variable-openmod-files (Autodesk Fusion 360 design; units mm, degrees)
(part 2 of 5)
sketch "Shell Hexagon Pattern" plane through (0, 0, 98) normal (0, 0, 1) x axis (-1, 0, 0)
  line L1 (19.1469, -26.6365) -> (22.8469, -28.7727)
  line L2 (19.1469, -22.3642) -> (19.1469, -26.6365)
  line L3 (22.8469, -20.228) -> (19.1469, -22.3642)
  line L4 (26.5469, -22.3642) -> (22.8469, -20.228)
  line L5 (26.5469, -26.6365) -> (26.5469, -22.3642)
  line L6 (22.8469, -28.7727) -> (26.5469, -26.6365)
  line L7 (-26.5469, 22.3642) -> (-22.8469, 20.228)
  line L8 (-26.5469, 26.6365) -> (-26.5469, 22.3642)
  line L9 (-22.8469, 28.7727) -> (-26.5469, 26.6365)
  line L10 (-19.1469, 26.6365) -> (-22.8469, 28.7727)
  line L11 (-19.1469, 22.3642) -> (-19.1469, 26.6365)
  line L12 (-22.8469, 20.228) -> (-19.1469, 22.3642)
  line L13 (19.1469, 22.3642) -> (22.8469, 20.228)
  line L14 (19.1469, 26.6365) -> (19.1469, 22.3642)
  line L15 (22.8469, 28.7727) -> (19.1469, 26.6365)
  line L16 (26.5469, 26.6365) -> (22.8469, 28.7727)
  line L17 (26.5469, 22.3642) -> (26.5469, 26.6365)
  line L18 (22.8469, 20.228) -> (26.5469, 22.3642)
  line L19 (-26.5469, -26.6365) -> (-22.8469, -28.7727)
  line L20 (-26.5469, -22.3642) -> (-26.5469, -26.6365)
  line L21 (-22.8469, -20.228) -> (-26.5469, -22.3642)
  line L22 (-19.1469, -22.3642) -> (-22.8469, -20.228)
  line L23 (-19.1469, -26.6365) -> (-19.1469, -22.3642)
  line L24 (-22.8469, -28.7727) -> (-19.1469, -26.6365)
  curve K1 (-7.3164, 50.178) -> (-7.3164, 50.178)
  line L25 (0, 51) -> (0, 0)
  line L26 (1, 24.5003) -> (0, 24.5003)
  line L27 (4.6, 24.5003) -> (1, 24.5003)
  line L28 (4.6, 20.3434) -> (1, 22.4219)
  line L29 (8.2, 22.4219) -> (4.6, 20.3434)
  line L30 (8.2, 26.5788) -> (8.2, 22.4219)
  line L31 (4.6, 28.6573) -> (8.2, 26.5788)
  line L32 (1, 26.5788) -> (4.6, 28.6573)
  line L33 (1, 22.4219) -> (1, 26.5788)
  line L34 (10.2, 24.5003) -> (8.2, 24.5003)
  line L35 (10.2, 26.5788) -> (13.8, 28.6573)
  line L36 (10.2, 22.4219) -> (10.2, 26.5788)
  line L37 (13.8, 20.3434) -> (10.2, 22.4219)
  line L38 (17.4, 22.4219) -> (13.8, 20.3434)
  line L39 (17.4, 26.5788) -> (17.4, 22.4219)
  line L40 (13.8, 28.6573) -> (17.4, 26.5788)
  line L41 (-1, 26.5788) -> (-1, 22.4219)
  line L42 (-4.6, 28.6573) -> (-1, 26.5788)
  line L43 (-8.2, 26.5788) -> (-4.6, 28.6573)
  line L44 (-8.2, 22.4219) -> (-8.2, 26.5788)
  line L45 (-4.6, 20.3434) -> (-8.2, 22.4219)
  line L46 (-1, 22.4219) -> (-4.6, 20.3434)
  line L47 (-13.8, 28.6573) -> (-10.2, 26.5788)
  line L48 (-17.4, 26.5788) -> (-13.8, 28.6573)
  line L49 (-17.4, 22.4219) -> (-17.4, 26.5788)
  line L50 (-13.8, 20.3434) -> (-17.4, 22.4219)
  line L51 (-10.2, 26.5788) -> (-10.2, 22.4219)
  line L52 (-10.2, 22.4219) -> (-13.8, 20.3434)
  line L53 (-1, 24.5003) -> (0, 24.5003)
  line L54 (16.6, 29.3501) -> (15.6, 27.618)
  line L55 (18.4, 28.3109) -> (14.8, 30.3893)
  line L56 (22, 30.3893) -> (18.4, 28.3109)
  line L57 (22, 34.5462) -> (22, 30.3893)
  line L58 (18.4, 36.6247) -> (22, 34.5462)
  line L59 (14.8, 34.5462) -> (18.4, 36.6247)
  line L60 (14.8, 30.3893) -> (14.8, 34.5462)
  line L61 (5.6, 30.3893) -> (5.6, 34.5462)
  line L62 (9.2, 28.3109) -> (5.6, 30.3893)
  line L63 (12.8, 30.3893) -> (9.2, 28.3109)
  line L64 (12.8, 34.5462) -> (12.8, 30.3893)
  line L65 (5.6, 34.5462) -> (9.2, 36.6247)
  line L66 (9.2, 36.6247) -> (12.8, 34.5462)
  line L67 (-3.6, 30.3893) -> (-3.6, 34.5462)
  line L68 (0, 28.3109) -> (-3.6, 30.3893)
  line L69 (3.6, 30.3893) -> (0, 28.3109)
  line L70 (3.6, 34.5462) -> (3.6, 30.3893)
  line L71 (-3.6, 34.5462) -> (0, 36.6247)
  line L72 (0, 36.6247) -> (3.6, 34.5462)
  line L73 (-12.8, 30.3893) -> (-12.8, 34.5462)
  line L74 (-9.2, 28.3109) -> (-12.8, 30.3893)
  line L75 (-5.6, 30.3893) -> (-9.2, 28.3109)
  line L76 (-5.6, 34.5462) -> (-5.6, 30.3893)
  line L77 (-12.8, 34.5462) -> (-9.2, 36.6247)
  line L78 (-9.2, 36.6247) -> (-5.6, 34.5462)
  line L79 (-14.8, 32.4678) -> (-12.8, 32.4678)
  line L80 (-27.6, 28.3109) -> (-31.2, 30.3893)
  line L81 (-24, 30.3893) -> (-27.6, 28.3109)
  line L82 (-24, 34.5462) -> (-24, 30.3893)
  line L83 (-27.6, 36.6247) -> (-24, 34.5462)
  line L84 (-31.2, 30.3893) -> (-31.2, 34.5462)
  line L85 (-31.2, 34.5462) -> (-27.6, 36.6247)
  line L86 (-18.4, 28.3109) -> (-22, 30.3893)
  line L87 (-14.8, 30.3893) -> (-18.4, 28.3109)
  line L88 (-14.8, 34.5462) -> (-14.8, 30.3893)
  line L89 (-18.4, 36.6247) -> (-14.8, 34.5462)
  line L90 (-22, 30.3893) -> (-22, 34.5462)
  line L91 (-22, 34.5462) -> (-18.4, 36.6247)
  line L92 (24, 32.4678) -> (22, 32.4678)
  line L93 (24, 34.5462) -> (27.6, 36.6247)
  line L94 (24, 30.3893) -> (24, 34.5462)
  line L95 (27.6, 28.3109) -> (24, 30.3893)
  line L96 (31.2, 30.3893) -> (27.6, 28.3109)
  line L97 (31.2, 34.5462) -> (31.2, 30.3893)
  line L98 (27.6, 36.6247) -> (31.2, 34.5462)
  line L99 (30.4, 27.618) -> (29.4, 29.3501)
  line L100 (32.2, 28.6573) -> (35.8, 26.5788)
  line L101 (28.6, 26.5788) -> (32.2, 28.6573)
  line L102 (28.6, 22.4219) -> (28.6, 26.5788)
  line L103 (32.2, 20.3434) -> (28.6, 22.4219)
  line L104 (35.8, 22.4219) -> (32.2, 20.3434)
  line L105 (35.8, 26.5788) -> (35.8, 22.4219)
  line L106 (15.6, 37.3175) -> (16.6, 35.5855)
  line L107 (23, 36.2783) -> (19.4, 38.3568)
  line L108 (26.6, 38.3568) -> (23, 36.2783)
  line L109 (26.6, 42.5137) -> (26.6, 38.3568)
  line L110 (23, 44.5921) -> (26.6, 42.5137)
  line L111 (19.4, 42.5137) -> (23, 44.5921)
  line L112 (19.4, 38.3568) -> (19.4, 42.5137)
  line L113 (10.2, 38.3568) -> (10.2, 42.5137)
  line L114 (13.8, 36.2783) -> (10.2, 38.3568)
  line L115 (17.4, 38.3568) -> (13.8, 36.2783)
  line L116 (17.4, 42.5137) -> (17.4, 38.3568)
  line L117 (10.2, 42.5137) -> (13.8, 44.5921)
  line L118 (13.8, 44.5921) -> (17.4, 42.5137)
  line L119 (1, 38.3568) -> (1, 42.5137)
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  point P1 (0, 0)
  point P28 (0, 0)
  point P29 (0, 51)
  point P30 (0, 24.5003)
  point P32 (4.6, 24.5003)
  point P39 (4.6, 24.5003)
  point P40 (8.2, 24.5003)
  point P62 (15.6, 27.618)
  point P88 (-12.8, 32.4678)
  point P102 (22, 32.4678)
  point P110 (29.4, 29.3501)
  point P118 (16.6, 35.5855)
  point P188 (15.6, 21.3827)
  point P232 (-29.4, 29.3501)
  point P557 (0, 0)
  point P593 (0, 0)
  point P425 (-4.6, -24.5003)
  point P534 (-4.6, -24.5003)
  point P31 (1, 24.5003)
  point P41 (10.2, 24.5003)
  point P54 (-1, 24.5003)
  point P61 (0, 24.5003)
  point P63 (16.6, 29.3501)
  point P89 (-14.8, 32.4678)
  point P103 (24, 32.4678)
  point P111 (30.4, 27.618)
  point P119 (15.6, 37.3175)
  point P156 (6.4, 43.5529)
  point P157 (7.4, 45.285)
  point P189 (16.6, 19.6506)
  point P233 (-30.4, 27.618)
  point P252 (29.4, 13.4152)
  point P253 (30.4, 11.6832)
  point P308 (-35.8, 8.5655)
  point P309 (-37.8, 8.5655)
  point P316 (30.4, 5.4478)
  point P317 (29.4, 3.7157)
  point P441 (-1, -24.5003)
  point P716 (0, -24.5003)
  point P423 (-10.2, -24.5003)
  point P424 (-8.2, -24.5003)
  point P571 (0, -24.5003)
  point P701 (1, -24.5003)
  point P535 (-15.6, -27.618)
  point P537 (-16.6, -29.3501)
  point P717 (12.8, -32.4678)
  point P729 (14.8, -32.4678)
  point P547 (-22, -32.4678)
  point P548 (-24, -32.4678)
  point P549 (-29.4, -29.3501)
  point P550 (-30.4, -27.618)
  point P541 (-16.6, -35.5855)
  point P558 (-15.6, -37.3175)
  point P536 (-7.4, -45.285)
  point P559 (-6.4, -43.5529)
  point P712 (-16.6, -19.6506)
  point P714 (-15.6, -21.3827)
  point P484 (30.4, -27.618)
  point P488 (29.4, -29.3501)
  point P560 (-29.4, -13.4152)
  point P561 (-30.4, -11.6832)
  point P563 (35.8, -8.5655)
  point P564 (37.8, -8.5655)
  point P562 (-30.4, -5.4478)
  point P565 (-29.4, -3.7157)
  coincident P1 P28
  coincident K1 P29
  vertical L25
  coincident L25 P30
  perpendicular L25 L26
  parallel L26 L27
  coincident P32 P39
  midpoint L30 P40
  perpendicular L30 L34
  midpoint L40 P62
  perpendicular L40 L54
  midpoint L73 P88
  perpendicular L73 L79
  midpoint L57 P102
  perpendicular L57 L92
  midpoint L96 P110
  perpendicular L96 L99
  midpoint L59 P118
  perpendicular L59 L106
  midpoint L38 P188
  midpoint L80 P232
  coincident P557 P593
  coincident P425 P534
  dimension "d175" distance P30 P31 = 1
  dimension "d180" distance P31 P32 = 3.6
  dimension "d181" distance P39 L33 = 3.6
  dimension "d182" distance P40 P41 = 2
  dimension "d183" distance P54 P61 = 1
  dimension "d184" distance P62 P63 = 2
  dimension "d185" distance P88 P89 = 2
  dimension "d186" distance P102 P103 = 2
  dimension "d187" distance P110 P111 = 2
  dimension "d188" distance P118 P119 = 2
  dimension "d189" distance P156 P157 = 2
  dimension "d190" distance P188 P189 = 2
  dimension "d191" distance P232 P233 = 2
  dimension "d192" distance P252 P253 = 2
  dimension "d193" distance P308 P309 = 2
  dimension "d194" distance P316 P317 = 2
  dimension "d195" distance P441 P716 = 1
  dimension "d196" distance P425 P441 = 3.6
  dimension "d197" distance = 3.6
  dimension "d198" distance P423 P424 = 2
  dimension "d199" distance P571 P701 = 1
  dimension "d200" distance P535 P537 = 2
  dimension "d201" distance P717 P729 = 2
  dimension "d202" distance P547 P548 = 2
  dimension "d203" distance P549 P550 = 2
  dimension "d204" distance P541 P558 = 2
  dimension "d205" distance P536 P559 = 2
  dimension "d206" distance P712 P714 = 2
  dimension "d207" distance P484 P488 = 2
  dimension "d208" distance P560 P561 = 2
  dimension "d209" distance P563 P564 = 2
  dimension "d210" distance P562 P565 = 2
sketch "Sketch12" plane through (0, 0, 98) normal (0, 0, 1) x axis (-1, 0, 0)
  line L1 (19.1469, -26.6365) -> (22.8469, -28.7727)
  line L2 (19.1469, -22.3642) -> (19.1469, -26.6365)
  line L3 (22.8469, -20.228) -> (19.1469, -22.3642)
  line L4 (26.5469, -22.3642) -> (22.8469, -20.228)
  line L5 (26.5469, -26.6365) -> (26.5469, -22.3642)
  line L6 (22.8469, -28.7727) -> (26.5469, -26.6365)
  line L7 (-26.5469, 22.3642) -> (-22.8469, 20.228)
  line L8 (-26.5469, 26.6365) -> (-26.5469, 22.3642)
  line L9 (-22.8469, 28.7727) -> (-26.5469, 26.6365)
  line L10 (-19.1469, 26.6365) -> (-22.8469, 28.7727)
  line L11 (-19.1469, 22.3642) -> (-19.1469, 26.6365)
  line L12 (-22.8469, 20.228) -> (-19.1469, 22.3642)
  line L13 (19.1469, 22.3642) -> (22.8469, 20.228)
  line L14 (19.1469, 26.6365) -> (19.1469, 22.3642)
  line L15 (22.8469, 28.7727) -> (19.1469, 26.6365)
  line L16 (26.5469, 26.6365) -> (22.8469, 28.7727)
  line L17 (26.5469, 22.3642) -> (26.5469, 26.6365)
  line L18 (22.8469, 20.228) -> (26.5469, 22.3642)
  line L19 (-26.5469, -26.6365) -> (-22.8469, -28.7727)
  line L20 (-26.5469, -22.3642) -> (-26.5469, -26.6365)
  line L21 (-22.8469, -20.228) -> (-26.5469, -22.3642)
  line L22 (-19.1469, -22.3642) -> (-22.8469, -20.228)
  line L23 (-19.1469, -26.6365) -> (-19.1469, -22.3642)
  line L24 (-22.8469, -28.7727) -> (-19.1469, -26.6365)
  curve K1 (-7.3164, 50.178) -> (-7.3164, 50.178)
  curve K2 (0, -48.6) -> (0, 48.6)
  curve K3 (38.6, 0) -> (-38.6, 0)
  closed curve K4 centre (0, 0)
  point P29 (0, 48.6)
  point P30 (0, -48.6)
  point P31 (-38.6, 0)
  point P32 (38.6, 0)
  coincident K4 P29
  coincident K4 P30
  coincident K4 P31
  coincident K4 P32
  dimension "d217" distance K4 = 97.2
  dimension "d218" = 77.2
extrude "Extrude25" cut sketch "Sketch12" profile of L1 L2 L3 L4 L5 L6 L7 L8 L9 L10 L11 L12 L13 L14 L15 L16 L17 L18 L19 L20 L21 L22 L23 L24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 against normal blind 4 bodies "Closed Shell (1) (1)", "Closed Shell (1) (2)", "Closed Shell (1) (3)", "Open Shell"
extrude "Extrude26" add sketch "Shell Hexagon Pattern" against normal blind 4 bodies "Closed Shell (1)", "Closed Shell (1) (1)", "Closed Shell (1) (2)", "Closed Shell (1) (3)"
chamfer "Chamfer8" distance 0.24 distance 1
sketch "Headband Arc" plane through (0, 0, 0) normal (0, 0, 1) x axis (1, 0, 0)
  line L1 (0, -165) -> (0, -75)
  line L2 (85, -165) -> (0, -165)
  line L3 (0, -71.5) -> (0, -75)
  line L4 (88.5, -165) -> (85, -165)
  line L5 (91.4952, -168.75) -> (85, -165)
  line L6 (92.5, -165) -> (85, -165)
  line L7 (81.4952, -186.0705) -> (91.4952, -168.75)
  line L8 (69.8038, -179.3205) -> (81.4952, -186.0705)
  line L9 (73.3038, -173.2583) -> (69.8038, -179.3205)
  line L10 (77.7713, -183.9205) -> (87.7713, -166.6)
  line L11 (81.2713, -177.8583) -> (73.3038, -173.2583)
  line L12 (87.2289, -149.2103) -> (91.4952, -168.75)
  closed curve K1 centre (0, -165)
  closed curve K2 centre (0, -165)
  point P4 (85, -165)
  point P7 (88.5, -165)
  point P16 (81.2713, -177.8583)
  point P17 (87.2289, -149.2103)
  point P18 (84.7553, -171.8238)
  point P19 (88.4796, -167.0089)
  point P2 (0, -75)
  point P3 (0, -165)
  point P6 (0, -71.5)
  point P9 (91.4952, -168.75)
  point P11 (81.4952, -186.0705)
  point P12 (69.8038, -179.3205)
  point P13 (73.3038, -173.2583)
  vertical L1
  perpendicular L1 L2
  coincident P4 K1
  parallel L1 L3
  parallel L2 L4
  coincident P7 K2
  horizontal L6
  perpendicular L5 L7
  perpendicular L7 L8
  perpendicular L8 L9
  coincident L10 P16
  perpendicular L10 L11
  coincident P17 K2
  coincident L10 P18
  coincident L5 P19
  dimension "d225" distance P2 P3 = 90
  dimension "d226" distance P3 P4 = 85
  dimension "d227" distance P2 P6 = 3.5
  dimension "d228" distance P4 P7 = 3.5
  dimension "d229" angle L5 L6 = 30
  dimension "d230" distance P4 P9 = 7.5
  dimension "d231" distance P9 P11 = 20
  dimension "d232" distance P11 P12 = 13.5
  dimension "d233" distance P12 P13 = 7
  dimension "d234" = 4.3
  dimension "d235" distance P9 P17 = 20
extrude "Extrude1" new body sketch "Headband Arc" profile of K1 L3 L4 K2 L5 L7 L8 L9 L10 L11 L12 along normal blind 36
sketch "Yoke Hole" plane through (-60.1971, -104.2644, 0) normal (-0.5, -0.866, 0) x axis (0.866, -0.5, 0)
  line L1 (163.6122, 0) -> (150.1122, 0)
  line L2 (163.6122, 36) -> (163.6122, 0)
  line L3 (150.1122, 36) -> (163.6122, 36)
  line L4 (150.1122, 0) -> (150.1122, 36)
  line L5 (152.6122, 18) -> (150.1122, 18)
  line L6 (155.7122, 18) -> (152.6122, 18)
  line L7 (152.6122, 14.9) -> (158.8122, 14.9)
  line L8 (152.6122, 21.1) -> (152.6122, 14.9)
  line L9 (158.8122, 21.1) -> (152.6122, 21.1)
  line L10 (158.8122, 14.9) -> (158.8122, 21.1)
  line L11 (152.6122, 21.1) -> (158.8122, 14.9)
  line L12 (158.8122, 21.1) -> (152.6122, 14.9)
  circle C1 centre (155.7122, 18) radius 3.1
  circle C2 centre (155.7122, 18) radius 2.1
  point P6 (150.1122, 18)
  point P13 (155.7122, 18)
  point P8 (155.7122, 18)
  point P14 (155.7122, 18)
  point P7 (152.6122, 18)
  point P15 (155.7122, 18)
  point P11 (152.6122, 21.1)
  point P12 (158.8122, 21.1)
  point P10 (152.6122, 14.9)
  midpoint L4 P6
  perpendicular L4 L5
  parallel L5 L6
  horizontal L7
  perpendicular L7 L8
  parallel L7 L9
  parallel L8 L10
  coincident L11 P13
  coincident L12 P13
  coincident P8 P13
  coincident P13 P14
  coincident P7 C1
  coincident P13 P15
  dimension "d240" distance P6 P7 = 2.5
  dimension "d241" distance P7 P8 = 3.1
  dimension "d242" distance P11 P12 = 6.2
  dimension "d243" distance P10 P11 = 6.2
  dimension "d244" diameter C2 = 4.2
extrude "Extrude2" cut sketch "Yoke Hole" profile of C2 against normal blind 7
extrude "Extrude3" cut sketch "Yoke Hole" profile of L7 L8 L9 C1 C2 against normal blind 5
sketch "Sketch2" plane through (141.6923, -81.8061, 0) normal (0.866, -0.5, 0) x axis (0.5, 0.866, 0)
  line L1 (-100.3942, 0) -> (-120.3942, 0)
  line L2 (-100.3942, 36) -> (-100.3942, 0)
  line L3 (-120.3942, 36) -> (-100.3942, 36)
  line L4 (-120.3942, 0) -> (-120.3942, 36)
  line L5 (-120.3942, 35) -> (-100.3942, 1)
  line L6 (-105.6231, 35.681) -> (-117.6911, 23.613)
  line L7 (-100.3942, 1) -> (-100.3942, 35)
  line L8 (-103.0973, 12.387) -> (-114.3233, 23.613)
  line L9 (-103.9392, 33.9971) -> (-114.3233, 23.613)
  line L10 (-113.2007, 12.387) -> (-120.217, 19.4033)
  line L11 (-100.3942, 35) -> (-120.3942, 35)
  line L12 (-106.4651, 12.387) -> (-117.6911, 23.613)
  line L13 (-120.3942, 36) -> (-100.3942, 36)
  line L14 (-120.217, 5.3707) -> (-113.2007, 12.387)
  line L15 (-100.5714, 30.6293) -> (-107.5877, 23.613)
  line L16 (-115.1653, 0.319) -> (-103.0973, 12.387)
  line L17 (-118.5331, 21.0872) -> (-118.5331, 3.6868)
  line L18 (-118.5331, 3.6868) -> (-107.307, 14.9128)
  line L19 (-100.3942, 0) -> (-120.3942, 0)
  line L20 (-107.307, 33.9971) -> (-103.9392, 33.9971)
  line L21 (-120.3942, 1) -> (-100.3942, 1)
  line L22 (-113.4813, 2.0029) -> (-116.8492, 2.0029)
  line L23 (-116.8492, 2.0029) -> (-106.4651, 12.387)
  line L24 (-102.2553, 32.3132) -> (-102.2553, 14.9128)
  line L25 (-102.2553, 14.9128) -> (-110.9555, 23.613)
  line L26 (-108.7103, 18) -> (-112.0781, 18)
  line L27 (-107.307, 9.8611) -> (-118.5331, 21.0872)
  line L28 (-120.3942, 35) -> (-120.3942, 1)
  line L29 (-100.5714, 16.5967) -> (-107.5877, 23.613)
  line L30 (-100.3942, 35) -> (-120.3942, 1)
  line L31 (-102.2553, 32.3132) -> (-110.9555, 23.613)
  line L32 (-100.3942, 36) -> (-100.3942, 0)
  line L33 (-120.3942, 0) -> (-120.3942, 36)
  point P11 (-113.4813, 2.0029)
  point P23 (-107.307, 33.9971)
  point P38 (-112.0781, 18)
  point P37 (-108.7103, 18)
  point P36 (-110.3942, 18)
  point P33 (-120.3942, 35)
  point P35 (-100.3942, 35)
  point P39 (-120.3942, 1)
  coincident P11 L16
  coincident P23 L6
  parallel L20 L22
  midpoint P38 L12
  midpoint P37 L8
  horizontal L21
  perpendicular L21 L28
  parallel L11 L21
  parallel L7 L28
  coincident P36 L5
  coincident P36 L30
  midpoint P36 L26
  dimension "d249" distance P33 P35 = 20
  dimension "d250" distance P33 P39 = 34
sketch "Left" plane through (52.1639, 11.3894, 0) normal (0.977, 0.2133, 0) x axis (-0.2133, 0.977, 0)
  dimension "d253" = 15
sketch "Sketch4" plane through (0, 0, 36) normal (0, 0, 1) x axis (-1, 0, 0)
  line L1 (-91.4952, 168.75) -> (-81.4952, 186.0705)
  line L2 (-87.2289, 149.2103) -> (-91.4952, 168.75)
  line L3 (0, 75) -> (0, 71.5)
  line L4 (-81.2713, 177.8583) -> (-84.7553, 171.8238)
  line L5 (-73.3038, 173.2583) -> (-81.2713, 177.8583)
  line L6 (-69.8038, 179.3205) -> (-73.3038, 173.2583)
  line L7 (-81.4952, 186.0705) -> (-69.8038, 179.3205)
  line L8 (-86.3713, 169.0249) -> (-81.2713, 177.8583)
  line L9 (-84.7531, 158.1446) -> (-86.3713, 169.0249)
  closed curve K1 centre (0, 165)
  closed curve K2 centre (0, 165)
  point P9 (-81.2713, 177.8583)
  point P12 (-81.2713, 177.8583)
  point P14 (-84.7531, 158.1446)
  point P13 (-86.3713, 169.0249)
  coincident P9 P12
  perpendicular L5 L8
  coincident K2 P14
  dimension "d258" distance P12 P13 = 10.2
  dimension "d259" distance P13 P14 = 11
chamfer "Chamfer1" distance 1 distance 1
extrude "Extrude6" cut sketch "Sketch4" profile of K2 L8 L9 against normal blind 36
sketch "Sketch12" plane through (-56.6971, -98.2023, 0) normal (0.5, 0.866, 0) x axis (-0.866, 0.5, 0)
  line L1 (-150.1122, 1) -> (-151.1122, 0)
  line L2 (-150.1122, 35) -> (-150.1122, 1)
  line L3 (-151.1122, 36) -> (-150.1122, 35)
  line L4 (-159.3122, 36) -> (-151.1122, 36)
  line L5 (-159.3122, 0) -> (-159.3122, 36)
  line L6 (-151.1122, 0) -> (-159.3122, 0)
  line L7 (-151.5552, 18) -> (-153.6337, 14.4)
  line L8 (-153.6337, 21.6) -> (-151.5552, 18)
  line L9 (-157.7906, 21.6) -> (-153.6337, 21.6)
  line L10 (-159.8691, 18) -> (-157.7906, 21.6)
  line L11 (-157.7906, 14.4) -> (-159.8691, 18)
  line L12 (-153.6337, 14.4) -> (-157.7906, 14.4)
  circle C1 centre (-155.7122, 18) radius 2.1
  point P8 (-155.7122, 18)
  point P15 (-155.7122, 18)
  coincident P8 P15
  dimension "d341" distance P15 L12 = 3.6
extrude "Extrude19" cut sketch "Sketch12" profile of L5 L10 L11 along normal blind 6
extrude "Extrude20" add sketch "Sketch12" profile of L5 L10 L11 along normal blind 2
mirror "Mirror1" mirrorStitchTolerance 0.1
sketch "Sketch5" plane through (-141.6923, -81.8061, 0) normal (-0.866, -0.5, 0) x axis (0.5, -0.866, 0)
  line L1 (120.3942, 1) -> (100.3942, 1)
  line L2 (120.3942, 35) -> (120.3942, 1)
  line L3 (100.3942, 35) -> (120.3942, 35)
  line L4 (100.3942, 1) -> (100.3942, 35)
  line L5 (108.7103, 18) -> (112.0781, 18)
  line L6 (120.3942, 35) -> (100.3942, 35)
  line L7 (100.3942, 1) -> (120.3942, 1)
  line L8 (120.3942, 0) -> (100.3942, 0)
  line L9 (103.9392, 2.0029) -> (114.3233, 12.387)
  line L10 (100.3942, 36) -> (120.3942, 36)
  line L11 (100.3942, 0) -> (100.3942, 36)
  line L12 (118.5331, 14.9128) -> (118.5331, 32.3132)
  line L13 (102.2553, 3.6868) -> (110.9555, 12.387)
  line L14 (120.3942, 36) -> (120.3942, 0)
  line L15 (120.217, 30.6293) -> (113.2007, 23.613)
  line L16 (100.3942, 0) -> (100.3942, 36)
  line L17 (100.5714, 19.4033) -> (107.5877, 12.387)
  line L18 (103.0973, 23.613) -> (114.3233, 12.387)
  line L19 (100.3942, 36) -> (120.3942, 36)
  line L20 (118.5331, 32.3132) -> (107.307, 21.0872)
  line L21 (106.4651, 23.613) -> (117.6911, 12.387)
  line L22 (102.2553, 3.6868) -> (102.2553, 21.0872)
  line L23 (120.3942, 1) -> (120.3942, 35)
  line L24 (100.3942, 1) -> (120.3942, 35)
  line L25 (107.307, 26.1389) -> (118.5331, 14.9128)
  line L26 (120.3942, 0) -> (100.3942, 0)
  line L27 (105.6231, 0.319) -> (117.6911, 12.387)
  line L28 (100.3942, 35) -> (100.3942, 1)
  line L29 (113.4813, 33.9971) -> (116.8492, 33.9971)
  line L30 (113.2007, 23.613) -> (120.217, 16.5967)
  line L31 (120.3942, 36) -> (120.3942, 0)
  line L32 (100.5714, 5.3707) -> (107.5877, 12.387)
  line L33 (115.1653, 35.681) -> (103.0973, 23.613)
  line L34 (102.2553, 21.0872) -> (110.9555, 12.387)
  line L35 (116.8492, 33.9971) -> (106.4651, 23.613)
  line L36 (120.3942, 1) -> (100.3942, 35)
  line L37 (107.307, 2.0029) -> (103.9392, 2.0029)
  point P26 (113.4813, 33.9971)
  point P27 (107.307, 2.0029)
  point P28 (112.0781, 18)
  point P36 (108.7103, 18)
  point P35 (110.3942, 18)
  point P29 (120.3942, 1)
  point P31 (100.3942, 1)
  point P43 (120.3942, 35)
  coincident P26 L33
  coincident P27 L27
  parallel L29 L37
  midpoint P28 L21
  midpoint P36 L18
  perpendicular L6 L23
  parallel L6 L7
  parallel L23 L28
  coincident P35 L36
  coincident P35 L24
  midpoint P35 L5
  dimension "d264" distance P29 P31 = 20
  dimension "d265" distance P29 P43 = 34
sketch "Right" plane through (-52.1639, 11.3894, 0) normal (-0.977, 0.2133, 0) x axis (-0.2133, -0.977, 0)
  line L1 (184.3831, 1) -> (164.3831, 1)
  line L2 (184.3831, 35) -> (184.3831, 1)
  line L3 (164.3831, 35) -> (184.3831, 35)
  line L4 (164.3831, 1) -> (164.3831, 35)
  line L5 (184.3831, 36) -> (184.3831, 0)
  line L6 (164.3831, 36) -> (184.3831, 36)
  curve K1
  curve K2
  curve K3
  curve K4
  line L7 (164.3831, 0) -> (164.3831, 36)
  line L8 (184.3831, 0) -> (164.3831, 0)
  dimension "d266" Text1-Height = 15
extrude "Extrude7" cut sketch "Left" against normal blind 0.5
extrude "Extrude8" cut sketch "Sketch2" profile of L6 L8 L9 L10 L12 L14 L15 L16 L17 L18 L20 L22 L23 L24 L25 L27 L29 L31 against normal blind 0.5
extrude "Extrude9" cut sketch "Right" against normal blind 0.5
extrude "Extrude10" cut sketch "Sketch5" profile of L9 L12 L13 L15 L17 L18 L20 L21 L22 L25 L27 L29 L30 L32 L33 L34 L35 L37 against normal blind 0.5
sketch "Yoke" plane through (0, 0, 0) normal (0, 0, 1) x axis (1, 0, 0)
  line L1 (50, -150) -> (45, -150)
  line L2 (0, -90) -> (0, -95)
  line L3 (50, -150) -> (45, -150)
  line L4 (50, -155) -> (50, -150)
  line L5 (45, -155) -> (50, -155)
  line L6 (45, -150) -> (45, -155)
  line L7 (39, -155) -> (50, -155)
  line L8 (39, -161) -> (39, -155)
  line L9 (50, -161) -> (39, -161)
  line L10 (50, -155) -> (50, -161)
  line L11 (18, -90) -> (0, -90)
  line L12 (18, -97) -> (18, -90)
  line L13 (0, -97) -> (18, -97)
  line L14 (0, -90) -> (0, -97)
  line L15 (30, -102) -> (18, -90)
  line L16 (34.9706, -90) -> (18, -90)
  line L17 (50, -155) -> (45, -155)
  line L18 (50, -158) -> (50, -155)
  line L19 (45, -158) -> (50, -158)
  line L20 (45, -155) -> (45, -158)
  closed curve K1 centre (0, -150)
  closed curve K2 centre (0, -150)
  point P17 (30, -102)
  point P20 (50, -158)
  point P4 (45, -150)
  point P8 (50, -150)
  point P10 (45, -155)
  point P9 (50, -155)
  point P11 (39, -155)
  point P13 (50, -161)
  point P6 (0, -90)
  point P14 (18, -90)
  point P16 (0, -97)
  concentric K1 K2
  horizontal L3
  vertical L4
  horizontal L5
  vertical L6
  horizontal L7
  vertical L8
  horizontal L9
  vertical L10
  horizontal L11
  vertical L12
  horizontal L13
  vertical L14
  horizontal L16
  coincident K1 P17
  horizontal L17
  vertical L18
  horizontal L19
  vertical L20
  midpoint L10 P20
  dimension "d275" distance K2 = 110
  dimension "d276" = 90
  dimension "d277" distance K1 = 120
  dimension "d278" = 100
  dimension "d279" distance P4 P8 = 5
  dimension "d280" distance P4 P10 = 5
  dimension "d281" distance P9 P11 = 11
  dimension "d282" distance P9 P13 = 6
  dimension "d283" distance P6 P14 = 18
  dimension "d284" distance P6 P16 = 7
  dimension "d285" angle L15 L16 = 45
extrude "Extrude11" new body sketch "Yoke" profile of L7 L8 L9 L10 L19 L20 along normal blind 6 bodies "Yoke"
extrude "Extrude12" add sketch "Yoke" profile of K2 K1 L1 L2 L3 L4 L5 L6 L7 L10 L11 L12 L13 L14 L15 L17 L18 L19 L20 along normal blind 10
chamfer "Chamfer3" distance 61 distance 4
fillet "Fillet2" radius 3
chamfer "Chamfer9" distance 1.5
sketch "Sketch9" plane through (0, -97, 0) normal (0, -1, 0) x axis (1, 0, 0)
  line L1 (12.0248, 0) -> (0, 0)
  line L2 (12.0248, 10) -> (12.0248, 0)
  line L3 (0, 10) -> (12.0248, 10)
  line L4 (0, 0) -> (0, 10)
  line L5 (5.5, 0) -> (0, 0)
  line L6 (5.5, 10) -> (5.5, 0)
  line L7 (0, 10) -> (5.5, 10)
  line L8 (0, 0) -> (0, 10)
  point P1 (0, 0)
  point P6 (0, 0)
  point P7 (5.5, 0)
  horizontal L5
  vertical L6
  horizontal L7
  vertical L8
  coincident P1 P6
  dimension "d302" distance P6 P7 = 5.5
extrude "Extrude15" cut sketch "Sketch9" profile of L1 L3 L4 L5 L6 L7 L8 against normal blind 2
mirror "Mirror2" mirrorStitchTolerance 0.1
sketch "Yoke socket" plane through (0, -95, 0) normal (0, -1, 0) x axis (1, 0, 0)
  line L1 (5.5, 0) -> (-5.5, 0)
  line L2 (5.5, 10) -> (5.5, 0)
  line L3 (-5.5, 10) -> (5.5, 10)
  line L4 (-5.5, 0) -> (-5.5, 10)
  line L5 (2.913, 6.0603) -> (-2.913, 3.9397)
  line L6 (4.6231, 1.3618) -> (2.913, 6.0603)
  line L7 (-1.2029, -0.7587) -> (4.6231, 1.3618)
  line L8 (-2.913, 3.9397) -> (-1.2029, -0.7587)
  line L9 (-4.6231, 1.3618) -> (1.2029, -0.7587)
  line L10 (-2.913, 6.0603) -> (-4.6231, 1.3618)
  line L11 (2.913, 3.9397) -> (-2.913, 6.0603)
  line L12 (1.2029, -0.7587) -> (2.913, 3.9397)
  line L13 (0, 1.5861) -> (0, 0.6861)
  line L14 (-1.613, 0.999) -> (0, 1.5861)
  line L15 (-1.7165, 1.5861) -> (0, 1.5861)
  line L16 (1.613, 0.999) -> (0, 1.5861)
  line L17 (1.7165, 1.5861) -> (0, 1.5861)
  circle C1 centre (0, 5) radius 3.1
  circle C2 centre (0, 5) radius 4.3139
  circle C3 centre (0, 5) radius 5
  point P6 (0, 5)
  point P10 (0, 5)
  point P11 (-2.913, 3.9397)
  point P19 (0, 0.6861)
  point P21 (-1.613, 0.999)
  point P23 (1.613, 0.999)
  point P12 (2.913, 6.0603)
  point P14 (-1.2029, -0.7587)
  point P16 (-2.913, 6.0603)
  point P17 (2.913, 3.9397)
  point P18 (-4.6231, 1.3618)
  point P20 (0, 1.5861)
  coincident P6 P10
  coincident C1 P11
  coincident C2 P19
  vertical L13
  horizontal L15
  coincident C2 P21
  horizontal L17
  coincident C2 P23
  dimension "d307" diameter C1 = 6.2
  dimension "d308" diameter C3 = 10
  dimension "d316" distance P11 P12 = 6.2
  dimension "d317" distance P11 P14 = 5
  dimension "d318" distance P16 P17 = 6.2
  dimension "d319" distance P16 P18 = 5
  dimension "d327" distance P19 P20 = 0.9
  dimension "d328" angle L14 L15 = 20
  dimension "d329" angle L16 L17 = 20
extrude "Extrude16" cut sketch "Yoke socket" profile of C1 C2 L6 L10 L14 L16 against normal blind 5
sketch "Screw Holder" plane through (0, 0, 0) normal (0, 0, 1) x axis (1, 0, 0)
  line L1 (3, -110) -> (-3, -110)
  line L2 (3, -113) -> (3, -110)
  line L3 (-3, -113) -> (3, -113)
  line L4 (-3, -110) -> (-3, -113)
  circle C1 centre (0, -110) radius 5
  circle C2 centre (0, -110) radius 2.1
  circle C3 centre (0, -110) radius 3
  point P5 (-3, -110)
  point P6 (3, -110)
  point P8 (-3, -113)
  concentric C1 C2
  concentric C1 C3
  horizontal L1
  vertical L2
  horizontal L3
  vertical L4
  coincident C3 P5
  dimension "d330" diameter C1 = 10
  dimension "d331" diameter C2 = 4.2
  dimension "d332" diameter C3 = 6
  dimension "d333" distance P5 P6 = 6
  dimension "d334" distance P5 P8 = 3
extrude "Extrude17" new body sketch "Screw Holder" profile of C1 C3 L2 L3 L4 along normal blind 2 bodies "Screw Holder"
extrude "Extrude18" add sketch "Screw Holder" profile of C2 C3 L2 L3 L4 along normal blind 12.2
sketch "Sketch13" plane through (0, 0, 0) normal (0, 0, 1) x axis (1, 0, 0)
  line L1 (-18, -134.6) -> (18, -134.6)
  line L2 (-18, -125.4) -> (-18, -134.6)
  line L3 (18, -125.4) -> (-18, -125.4)
  line L4 (18, -134.6) -> (18, -125.4)
  line L5 (-18, -125.4) -> (18, -134.6)
  line L6 (18, -125.4) -> (-18, -134.6)
  line L7 (-13, -134.6) -> (13, -134.6)
  line L8 (-13, -125.4) -> (-13, -134.6)
  line L9 (13, -125.4) -> (-13, -125.4)
  line L10 (13, -134.6) -> (13, -125.4)
  line L11 (-13, -125.4) -> (13, -134.6)
  line L12 (13, -125.4) -> (-13, -134.6)
  line L13 (-13, -133.6) -> (13, -133.6)
  line L14 (-13, -131.6) -> (13, -131.6)
  line L15 (0, -126.9) -> (0, -125.4)
  line L16 (0, -124.8431) -> (3.6, -126.9215)
  line L17 (-3.6, -126.9215) -> (0, -124.8431)
  line L18 (-3.6, -131.0785) -> (-3.6, -126.9215)
  line L19 (0, -133.1569) -> (-3.6, -131.0785)
  line L20 (3.6, -131.0785) -> (0, -133.1569)
  line L21 (3.6, -126.9215) -> (3.6, -131.0785)
  line L22 (3.6, -131.0785) -> (-3.6, -131.0785)
  line L23 (3.6, -134.6) -> (3.6, -131.0785)
  line L24 (-3.6, -134.6) -> (3.6, -134.6)
  line L25 (-3.6, -131.0785) -> (-3.6, -134.6)
  circle C1 centre (0, -129) radius 2.1
  point P6 (0, -130)
  point P11 (0, -130)
  point P16 (0, -125.4)
  point P17 (0, -126.9)
  point P18 (0, -129)
  point P25 (0, -129)
  point P4 (-18, -125.4)
  point P5 (18, -125.4)
  point P3 (-18, -134.6)
  point P9 (-13, -125.4)
  point P10 (13, -125.4)
  point P22 (-3.6, -131.0785)
  point P26 (3.6, -131.0785)
  horizontal L1
  perpendicular L1 L2
  parallel L1 L3
  parallel L2 L4
  coincident L5 P6
  coincident L6 P6
  horizontal L7
  perpendicular L7 L8
  parallel L7 L9
  parallel L8 L10
  coincident L11 P11
  coincident L12 P11
  coincident P6 P11
  midpoint L3 P16
  perpendicular L3 L15
  coincident P17 C1
  coincident P18 P25
  horizontal L22
  vertical L23
  horizontal L24
  vertical L25
  dimension "d346" distance P4 P5 = 36
  dimension "d347" distance P3 P4 = 9.2
  dimension "d348" distance P9 P10 = 26
  dimension "d349" = 1
  dimension "d350" = 3
  dimension "d351" distance P16 P17 = 1.5
  dimension "d352" diameter C1 = 4.2
  dimension "d353" distance P25 L21 = 3.6
  dimension "d354" distance P22 P26 = 7.2
extrude "Extrude21" new body sketch "Sketch13" profile of L1 L2 L3 L4 L7 L8 L9 L10 L13 L14 C1 L16 L17 L18 L21 L23 L24 L25 along normal blind 10 bodies "Headband Clip"
extrude "Extrude22" cut sketch "Sketch13" profile of L1 L3 L7 L9 L13 L14 C1 L16 L17 L18 L21 L23 L24 L25 along normal blind 6
extrude "Extrude23" cut sketch "Sketch13" profile of C1 along normal blind 8
extrude "Extrude24" add sketch "Sketch13" profile of L1 L3 L7 L9 L13 L14 C1 L16 L17 L18 L21 L23 L24 L25 along normal blind 2
sketch "Sketch15" plane through (0, -134.6, 0) normal (0, -1, 0) x axis (1, 0, 0)
  line L1 (18, 0) -> (-18, 0)
  line L2 (18, 10) -> (18, 0)
  line L3 (-18, 10) -> (18, 10)
  line L4 (-18, 0) -> (-18, 10)
  line L5 (-3.6, 6) -> (-3.6, 2)
  line L6 (3.6, 6) -> (-3.6, 6)
  line L7 (3.6, 2) -> (3.6, 6)
  line L8 (-3.6, 2) -> (3.6, 2)
  line L9 (-2, 8) -> (2, 8)
  line L10 (-2, 12) -> (-2, 8)
  line L11 (2, 12) -> (-2, 12)
  line L12 (2, 8) -> (2, 12)
  line L13 (-2, 12) -> (2, 8)
  line L14 (2, 12) -> (-2, 8)
  line L15 (-4, 10) -> (-2, 12)
  line L16 (4, 10) -> (2, 12)
  line L17 (0, 7) -> (0, 6)
  line L18 (0, 8.25) -> (0, 7)
  line L19 (-1.5, 7) -> (1.5, 7)
  line L20 (-1.5, 9.5) -> (-1.5, 7)
  line L21 (1.5, 9.5) -> (-1.5, 9.5)
  line L22 (1.5, 7) -> (1.5, 9.5)
  line L23 (-1.5, 9.5) -> (1.5, 7)
  line L24 (1.5, 9.5) -> (-1.5, 7)
  point P15 (0, 10)
  point P16 (-4, 10)
  point P17 (4, 10)
  point P18 (0, 6)
  point P25 (0, 8.25)
  point P20 (0, 8.25)
  point P13 (-2, 12)
  point P14 (2, 12)
  point P12 (-2, 8)
  point P19 (0, 7)
  point P23 (-1.5, 9.5)
  point P24 (1.5, 9.5)
  point P22 (-1.5, 7)
  horizontal L9
  perpendicular L9 L10
  parallel L9 L11
  parallel L10 L12
  coincident L13 P15
  coincident L14 P15
  midpoint L3 P15
  coincident L3 P16
  perpendicular L13 L15
  coincident L3 P17
  perpendicular L15 L16
  midpoint L6 P18
  perpendicular L6 L17
  parallel L17 L18
  horizontal L19
  perpendicular L19 L20
  parallel L19 L21
  parallel L20 L22
  coincident L23 P25
  coincident L24 P25
  coincident P20 P25
  dimension "d383" distance P13 P14 = 4
  dimension "d384" distance P12 P13 = 4
  dimension "d387" distance P18 P19 = 1
  dimension "d388" distance P19 P20 = 1.25
  dimension "d389" distance P23 P24 = 3
  dimension "d390" distance P22 P23 = 2.5
extrude "Extrude28" add sketch "Sketch15" profile of L3 L10 L11 L12 L15 L16 against normal blind 9.2
extrude "Extrude29" cut sketch "Sketch15" profile of L19 L20 L21 L22 against normal blind 3
sketch "Sketch16" plane through (0, 0, 12) normal (0, 0, 1) x axis (-1, 0, 0)
  line L1 (-2, 134.6) -> (2, 134.6)
  line L2 (-2, 125.4) -> (-2, 134.6)
  line L3 (2, 125.4) -> (-2, 125.4)
  line L4 (2, 134.6) -> (2, 125.4)
  line L5 (0, 130.6) -> (0, 134.6)
  line L6 (-1.5, 132.6) -> (1.5, 132.6)
  line L7 (-1.5, 128.6) -> (-1.5, 132.6)
  line L8 (1.5, 128.6) -> (-1.5, 128.6)
  line L9 (1.5, 132.6) -> (1.5, 128.6)
  line L10 (-1.5, 128.6) -> (1.5, 132.6)
  line L11 (1.5, 128.6) -> (-1.5, 132.6)
  point P6 (0, 134.6)
  point P12 (0, 130.6)
  point P7 (0, 130.6)
  point P10 (-1.5, 128.6)
  point P11 (1.5, 128.6)
  midpoint L1 P6
  perpendicular L1 L5
  horizontal L6
  perpendicular L6 L7
  parallel L6 L8
  parallel L7 L9
  coincident L10 P12
  coincident L11 P12
  coincident P7 P12
  dimension "d393" distance P6 P7 = 4
  dimension "d394" distance P10 P11 = 3
extrude "Extrude30" cut sketch "Sketch16" profile of L6 L7 L8 L9 against normal blind 2.5
sketch "Sketch17" plane through (1.5, 0, 0) normal (-1, 0, 0) x axis (0, -1, 0)
  line L1 (134.6, 9.5) -> (134.6, 7)
  line L2 (132.6, 9.5) -> (134.6, 9.5)
  line L3 (132.6, 12) -> (132.6, 9.5)
  line L4 (128.6, 12) -> (132.6, 12)
  line L5 (128.6, 9.5) -> (128.6, 12)
  line L6 (131.6, 9.5) -> (128.6, 9.5)
  line L7 (131.6, 7) -> (131.6, 9.5)
  line L8 (134.6, 7) -> (131.6, 7)
  line L9 (134.6, 7) -> (131.6, 9.5)
  line L10 (131.6, 9.5) -> (128.6, 12)
  line L11 (132.6, 11.5) -> (132.6, 12)
  line L12 (134.6, 9.5) -> (132.6, 11.5)
  point P8 (131.6, 9.5)
  point P10 (131.6, 9.5)
  point P2 (134.6, 7)
  point P11 (134.6, 7)
  point P6 (128.6, 12)
  point P12 (128.6, 12)
  point P5 (132.6, 12)
  point P13 (132.6, 12)
  point P3 (134.6, 9.5)
  point P15 (134.6, 9.5)
  point P14 (132.6, 11.5)
  coincident P8 P10
  coincident P2 P11
  coincident P6 P12
  coincident P5 P13
  perpendicular L4 L11
  coincident P3 P15
  dimension "d397" distance P13 P14 = 0.5
extrude "Extrude31" cut sketch "Sketch17" profile of L2 L3 L12 along normal blind 3
extrude "Extrude32" add sketch "Sketch17" profile of L5 L6 L7 L8 L9 L10 along normal blind 3
chamfer "Chamfer6" distance 2
chamfer "Chamfer7" distance 3.5
copy_paste_bodies "CopyPasteBodies3"
move "Move3"
work_plane "WorkPlane3" AlongDistance 0
sketch "Custom Shell" plane through (0, 0, 134) normal (0, 0, -1) x axis (-1, 0, 0)
  curve K1 (-35, 0) -> (35, 0)
  curve K2 (0, -45) -> (0, 45)
  curve K3 (0, 48.6) -> (0, -48.6)
  curve K4 (-38.6, 0) -> (38.6, 0)
  curve K5 (0, -45.5) -> (0, 45.5)
  curve K6 (35.5, 0) -> (-35.5, 0)
  closed curve K7 centre (0, 0)
  closed curve K8 centre (0, 0)
  closed curve K9 centre (0, 0)
  point P3 (35, 0)
  point P4 (-35, 0)
  point P5 (0, 45)
  point P6 (0, -45)
  point P1 (0, 0)
  point P2 (0, 0)
  point P8 (0, -48.6)
  point P9 (0, 48.6)
  point P10 (38.6, 0)
  point P11 (-38.6, 0)
  point P7 (0, 0)
  point P13 (0, 45.5)
  point P14 (0, -45.5)
  point P15 (-35.5, 0)
  point P16 (35.5, 0)
  point P12 (0, 0)
  coincident K7 P3
  coincident K7 P4
  coincident K7 P5
  coincident K7 P6
  coincident P1 P2
  horizontal K1
  coincident K8 P8
  coincident K8 P9
  coincident K8 P10
  coincident K8 P11
  coincident P1 P7
  perpendicular K1 K3
  coincident K9 P13
  coincident K9 P14
  coincident K9 P15
  coincident K9 P16
  coincident P1 P12
  perpendicular K4 K5
  dimension "d702" distance K7 = 70
  dimension "d703" = 90
  dimension "d704" distance K8 = 97.2
  dimension "d705" = 77.2
  dimension "d715" distance K9 = 91
  dimension "d716" = 71
extrude "Extrude44" cut sketch "Custom Shell" profile of K7 K8 against normal blind 4 bodies "Custom Shell Open Grill"
extrude "Extrude45" add sketch "Custom Shell" profile of K7 K8 against normal blind 4
chamfer "Chamfer12" distance 3
offset_faces "OffsetFaces3" distance -0.2
extrude "Extrude46" add sketch "Custom Shell" profile of K8 K9 against normal blind 3
chamfer "Chamfer14" distance 3
delete_face "DeleteFace1"
copy_paste_bodies "CopyPasteBodies4"
move "Move4"
sketch "Closed Shell" plane through (0, 0, 178) normal (0, 0, 1) x axis (-1, 0, 0)
  curve K1 (0, 48.4) -> (0, 48.4)
  line L1 (19.1469, -26.6365) -> (22.8469, -28.7727)
  line L2 (19.1469, -22.3642) -> (19.1469, -26.6365)
  line L3 (22.8469, -20.228) -> (19.1469, -22.3642)
  line L4 (26.5469, -22.3642) -> (22.8469, -20.228)
  line L5 (26.5469, -26.6365) -> (26.5469, -22.3642)
  line L6 (22.8469, -28.7727) -> (26.5469, -26.6365)
  line L7 (-19.1469, 22.3642) -> (-19.1469, 26.6365)
  line L8 (-22.8469, 20.228) -> (-19.1469, 22.3642)
  line L9 (-26.5469, 22.3642) -> (-22.8469, 20.228)
  line L10 (-26.5469, 26.6365) -> (-26.5469, 22.3642)
  line L11 (-22.8469, 28.7727) -> (-26.5469, 26.6365)
  line L12 (-19.1469, 26.6365) -> (-22.8469, 28.7727)
  line L13 (26.5469, 22.3642) -> (26.5469, 26.6365)
  line L14 (22.8469, 20.228) -> (26.5469, 22.3642)
  line L15 (19.1469, 22.3642) -> (22.8469, 20.228)
  line L16 (19.1469, 26.6365) -> (19.1469, 22.3642)
  line L17 (22.8469, 28.7727) -> (19.1469, 26.6365)
  line L18 (26.5469, 26.6365) -> (22.8469, 28.7727)
  line L19 (-19.1469, -22.3642) -> (-22.8469, -20.228)
  line L20 (-19.1469, -26.6365) -> (-19.1469, -22.3642)
  line L21 (-22.8469, -28.7727) -> (-19.1469, -26.6365)
  line L22 (-26.5469, -26.6365) -> (-22.8469, -28.7727)
  line L23 (-26.5469, -22.3642) -> (-26.5469, -26.6365)
  line L24 (-22.8469, -20.228) -> (-26.5469, -22.3642)
  curve K2 (0, 45) -> (0, -45)
  curve K3 (-35, 0) -> (35, 0)
  closed curve K4 centre (0, 0)
  point P29 (0, -45)
  point P30 (0, 45)
  point P31 (35, 0)
  point P32 (-35, 0)
  point P1 (0, 0)
  point P28 (0, 0)
  coincident K4 P29
  coincident K4 P30
  coincident K4 P31
  coincident K4 P32
  coincident P1 P28
  vertical K2
  dimension "d718" distance K4 = 90
  dimension "d719" = 70
extrude "Extrude47" add sketch "Closed Shell" profile of L1 L2 L3 L4 L5 L6 L7 L8 L9 L10 L11 L12 L13 L14 L15 L16 L17 L18 L19 L20 L21 L22 L23 L24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 against normal blind 4
fillet "Fillet1" radius 1
sketch "Sketch20" plane through (0, 0, 22) normal (0, 0, 1) x axis (-1, 0, 0)
  line L1 (-8, 54.1239) -> (-8, 51.8694)
  line L2 (8, 51.8694) -> (8, 54.1239)
  line L3 (17.2573, 46.032) -> (18.1032, 47.8443)
  line L4 (6, 53.0308) -> (6, 50.2477)
  line L5 (-6, 53.0308) -> (6, 53.0308)
  line L6 (-6, 50.2477) -> (-6, 53.0308)
  line L7 (-18.1032, 47.8443) -> (-17.2573, 46.032)
  line L8 (-27.3973, -19.1838) -> (-24.0432, -16.8352)
  line L9 (-24.0432, 16.8352) -> (-27.3973, 19.1838)
  line L10 (-17.8191, 17.8191) -> (-19.4454, 19.4454)
  line L11 (-8, 32.5308) -> (-8, 23.8964)
  line L12 (8, 23.8964) -> (8, 32.5308)
  line L13 (19.4454, 19.4454) -> (17.8191, 17.8191)
  line L14 (27.3973, 19.1838) -> (24.0432, 16.8352)
  line L15 (24.0432, -16.8352) -> (27.3973, -19.1838)
  line L16 (-15.6326, -25.0174) -> (-17.7523, -28.4096)
  line L17 (17.7523, -28.4096) -> (15.6326, -25.0174)
  line L18 (45, 5.5) -> (-45, 5.5)
  line L19 (45, -5.5) -> (45, 5.5)
  line L20 (-45, -5.5) -> (45, -5.5)
  line L21 (-45, 5.5) -> (-45, -5.5)
  line L22 (45, -5.5) -> (-45, 5.5)
  line L23 (-45, -5.5) -> (45, 5.5)
  line L24 (-37, 5.5) -> (-37, -5.5)
  line L25 (37, -5.5) -> (37, 5.5)
  closed curve K1 centre (0, 0)
  closed curve K2 centre (0, 0)
  closed curve K3 centre (0, 0)
  closed curve K4 centre (0, 0)
  closed curve K5 centre (0, 0)
  arc A1 centre (0, 0) radius 27.5 clockwise from (26.4189, -7.6348) to (-26.4189, -7.6348)
  closed curve K6 centre (0, 0)
  closed curve K7 centre (0, 0)
  closed curve K8 centre (0, 0)
  arc A2 centre (0, 0) radius 27.5 clockwise from (-26.4189, 7.6348) to (-19.4454, 19.4454)
  arc A3 centre (0, 0) radius 25.2 clockwise from (-17.8191, 17.8191) to (-8, 23.8964)
  arc A4 centre (0, 0) radius 33.5 clockwise from (-8, 32.5308) to (8, 32.5308)
  arc A5 centre (0, 0) radius 25.2 clockwise from (8, 23.8964) to (17.8191, 17.8191)
  arc A6 centre (0, 0) radius 27.5 clockwise from (19.4454, 19.4454) to (26.4189, 7.6348)
  closed curve K9 centre (0, 0)
  closed curve K10 centre (0, 0)
  closed curve K11 centre (0, 0)
  arc A7 centre (0, 0) radius 29.5 clockwise from (15.6326, -25.0174) to (-15.6326, -25.0174)
  arc A8 centre (0, 0) radius 33.5 clockwise from (17.7523, -28.4096) to (-17.7523, -28.4096)
  circle C1 centre (22.8469, 24.5003) radius 2.2
  circle C2 centre (22.8469, -24.5003) radius 2.2
  circle C3 centre (-22.8469, 24.5003) radius 2.2
  circle C4 centre (-22.8469, -24.5003) radius 2.2
  point P47 (0, 0)
  point P1 (0, 0)
  point P45 (45, -5.5)
  point P46 (-45, -5.5)
  point P44 (45, 5.5)
  horizontal L18
  perpendicular L18 L19
  parallel L18 L20
  parallel L19 L21
  coincident L22 P47
  coincident L23 P47
  coincident P1 P47
  dimension "d591" distance P45 P46 = 90
  dimension "d592" distance P44 P45 = 11
  dimension "d593" = 8
  dimension "d594" = 8
extrude "Extrude37" add sketch "Sketch20" profile of K1 L18 L19 L20 L21 L24 L25 along normal blind 9
extrude "Extrude38" add sketch "Sketch20" profile of K1 L18 L19 L20 L21 against normal blind 2
sketch "Sketch21" plane through (45, 0, 0) normal (1, 0, 0) x axis (0, 1, 0)
  line L1 (5.5, 31) -> (5.5, 20)
  line L2 (-5.5, 31) -> (5.5, 31)
  line L3 (-5.5, 20) -> (-5.5, 31)
  line L4 (5.5, 20) -> (-5.5, 20)
  line L5 (3.0075, 21) -> (3.0075, 20)
  line L6 (5.5, 31) -> (5.5, 20)
  line L7 (2.2627, 23.2373) -> (6.1518, 27.1263)
  line L8 (1.0945, 28.507) -> (-1.0945, 22.493)
  line L9 (-0.0255, 30) -> (-0.0255, 31)
  line L10 (-5.5, 31) -> (5.5, 31)
  line L11 (3.0075, 20) -> (4.0738, 20)
  line L12 (-5.5, 20) -> (-5.5, 22)
  line L13 (4.0738, 20) -> (4.0738, 21)
  line L14 (-5.5, 29) -> (-3.5, 29)
  line L15 (-3.5, 29) -> (-3.5, 31)
  line L16 (0.9745, 30) -> (-0.0255, 30)
  line L17 (-3.5, 20) -> (-5.5, 20)
  line L18 (-0.0255, 31) -> (0.9745, 31)
  line L19 (-5.5, 20) -> (-5.5, 31)
  line L20 (5.5, 20) -> (-5.5, 20)
  line L21 (6.1518, 27.1263) -> (1.6263, 31.6518)
  line L22 (0.9745, 31) -> (0.9745, 30)
  line L23 (1.6263, 31.6518) -> (-2.2627, 27.7627)
  line L24 (-2.2627, 27.7627) -> (2.2627, 23.2373)
  line L25 (-1.0945, 22.493) -> (4.0738, 20.6119)
  line L26 (-3.5, 31) -> (-5.5, 31)
  line L27 (-3.5, 22) -> (-3.5, 20)
  line L28 (6.2628, 26.6259) -> (1.0945, 28.507)
  line L29 (4.0738, 20.6119) -> (6.2628, 26.6259)
  line L30 (-5.5, 22) -> (-3.5, 22)
  line L31 (-5.5, 31) -> (-5.5, 29)
  line L32 (4.0738, 21) -> (3.0075, 21)
  circle C1 centre (-3.5, 29) radius 2
  circle C2 centre (-3.5, 22) radius 2
  circle C3 centre (0, 25.5) radius 3.2
  point P12 (1.0945, 28.507)
  point P28 (-0.0255, 30)
  point P20 (0.9745, 31)
  point P36 (3.0075, 21)
  point P30 (4.0738, 20)
  point P11 (-5.5, 31)
  point P29 (-5.5, 31)
  point P6 (-5.5, 20)
  point P10 (-5.5, 20)
  point P8 (-3.5, 22)
  point P26 (-3.5, 22)
  point P7 (-3.5, 20)
  point P25 (-3.5, 29)
  point P32 (-3.5, 29)
  point P27 (-3.5, 31)
  point P15 (-1.0945, 22.493)
  point P16 (2.2627, 23.2373)
  point P19 (-2.2627, 27.7627)
  point P31 (0.9745, 30)
  point P35 (4.0738, 21)
  point P33 (-5.5, 29)
  point P9 (-5.5, 22)
  coincident P12 C3
  horizontal L18
  vertical L9
  horizontal L16
  vertical L22
  coincident P28 L23
  coincident P20 L23
  coincident P20 L10
  horizontal L11
  vertical L5
  horizontal L32
  vertical L13
  coincident P36 L25
  coincident P30 L20
  horizontal L26
  vertical L15
  horizontal L14
  vertical L31
  coincident P11 P29
  horizontal L17
  vertical L27
  horizontal L30
  vertical L12
  coincident P6 P10
  coincident P8 P26
  coincident P7 C2
  coincident P25 P32
  coincident P27 C1
  dimension "d599" diameter C3 = 6.4
  dimension "d600" distance P12 P15 = 6.4
  dimension "d601" distance P16 P19 = 6.4
  dimension "d602" distance P20 P31 = 1
  dimension "d603" distance P30 P35 = 1
  dimension "d604" distance P27 P29 = 2
  dimension "d605" distance P29 P33 = 2
  dimension "d606" distance P6 P7 = 2
  dimension "d607" distance P6 P9 = 2
sketch "Sketch22" plane through (-45, 0, 0) normal (-1, 0, 0) x axis (0, -1, 0)
  line L1 (5.5, 31) -> (5.5, 20)
  line L2 (-5.5, 31) -> (5.5, 31)
  line L3 (-5.5, 20) -> (-5.5, 31)
  line L4 (5.5, 20) -> (-5.5, 20)
  line L5 (-1.0945, 28.507) -> (1.0945, 22.493)
  line L6 (-5.5, 31) -> (-5.5, 20)
  line L7 (3.5, 31) -> (5.5, 31)
  line L8 (5.5, 31) -> (-5.5, 31)
  line L9 (5.5, 20) -> (5.5, 31)
  line L10 (-2.2627, 23.2373) -> (-6.1518, 27.1263)
  line L11 (5.5, 20) -> (5.5, 22)
  line L12 (-6.1518, 27.1263) -> (-1.6263, 31.6518)
  line L13 (5.5, 31) -> (5.5, 29)
  line L14 (-3.0075, 21) -> (-3.0075, 20)
  line L15 (5.5, 22) -> (3.5, 22)
  line L16 (3.5, 22) -> (3.5, 20)
  line L17 (-0.9745, 31) -> (-0.9745, 30)
  line L18 (-4.0738, 20.6119) -> (-6.2628, 26.6259)
  line L19 (-1.6263, 31.6518) -> (2.2627, 27.7627)
  line L20 (0.0255, 30) -> (0.0255, 31)
  line L21 (-3.0075, 20) -> (-4.0738, 20)
  line L22 (-0.9745, 30) -> (0.0255, 30)
  line L23 (-6.2628, 26.6259) -> (-1.0945, 28.507)
  line L24 (5.5, 29) -> (3.5, 29)
  line L25 (-5.5, 31) -> (-5.5, 20)
  line L26 (-4.0738, 21) -> (-3.0075, 21)
  line L27 (5.5, 31) -> (-5.5, 31)
  line L28 (-5.5, 20) -> (5.5, 20)
  line L29 (1.0945, 22.493) -> (-4.0738, 20.6119)
  line L30 (3.5, 20) -> (5.5, 20)
  line L31 (2.2627, 27.7627) -> (-2.2627, 23.2373)
  line L32 (5.5, 20) -> (5.5, 31)
  line L33 (0.0255, 31) -> (-0.9745, 31)
  line L34 (-4.0738, 20) -> (-4.0738, 21)
  line L35 (-5.5, 20) -> (5.5, 20)
  line L36 (3.5, 29) -> (3.5, 31)
  circle C1 centre (3.5, 29) radius 2
  circle C2 centre (0, 25.5) radius 3.2
  circle C3 centre (3.5, 22) radius 2
  point P20 (-1.0945, 28.507)
  point P35 (0.0255, 30)
  point P17 (-0.9745, 31)
  point P29 (-3.0075, 21)
  point P37 (-4.0738, 20)
  point P15 (5.5, 31)
  point P36 (5.5, 31)
  point P6 (5.5, 20)
  point P10 (5.5, 20)
  point P9 (3.5, 22)
  point P33 (3.5, 22)
  point P7 (3.5, 20)
  point P30 (3.5, 29)
  point P39 (3.5, 29)
  point P34 (3.5, 31)
  point P18 (1.0945, 22.493)
  point P19 (-2.2627, 23.2373)
  point P23 (2.2627, 27.7627)
  point P40 (-0.9745, 30)
  point P26 (-4.0738, 21)
  point P28 (5.5, 29)
  point P8 (5.5, 22)
  coincident P20 C2
  coincident P35 L19
  coincident P17 L19
  coincident P17 L27
  coincident P29 L29
  coincident P37 L28
  coincident P15 P36
  coincident P6 P10
  coincident P9 P33
  coincident P7 C3
  coincident P30 P39
  coincident P34 C1
  dimension "d608" diameter C2 = 6.4
  dimension "d609" distance P18 P20 = 6.4
  dimension "d610" distance P19 P23 = 6.4
  dimension "d611" distance P17 P40 = 1
  dimension "d612" distance P26 P37 = 1
  dimension "d613" distance P34 P36 = 2
  dimension "d614" distance P28 P36 = 2
  dimension "d615" distance P6 P7 = 2
  dimension "d616" distance P6 P8 = 2
extrude "Extrude39" cut sketch "Sketch22" profile of C1 C2 C3 against normal blind 6
extrude "Extrude40" cut sketch "Sketch21" profile of C1 C2 C3 against normal blind 6
extrude "Extrude41" add sketch "Sketch21" profile of L2 L3 L4 L5 C1 L9 L10 C2 C3 L19 L20 L23 L25 along normal blind 3
extrude "Extrude42" add sketch "Sketch22" profile of L1 L2 L4 L8 L9 L14 L19 C1 C2 L20 C3 L27 L28 L29 L32 L35 along normal blind 3
fillet "Fillet5" radius 0.8
offset_faces "OffsetFaces2" distance 0.5
chamfer "Chamfer11" distance 1.5 Rotate Angle 50
copy_paste_bodies "CopyPasteBodies1"
move "Move1"
copy_paste_bodies "CopyPasteBodies2"
move "Move2"
component_from_bodies "Body->Comp2"
copy_paste_bodies "CutPasteBodies1"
